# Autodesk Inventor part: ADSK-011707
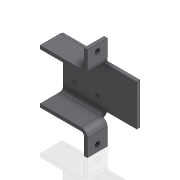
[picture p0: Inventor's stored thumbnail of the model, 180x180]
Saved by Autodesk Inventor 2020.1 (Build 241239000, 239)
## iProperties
Created: 2000-03
Part Number: ADSK-011707
Material: 1.0312 DC05
Document SubType Name: Tôlerie
Designer: cmcgourin
Density: 1 g/cm^3
Sheet Metal Rule: Stahlblech 1.0312 - DC05 -   6.0 mm
Appearance: Metal-Steel(Polish)
Mass: 133.774 g
Surface Area: 504.03 cm^2
Volume: 133.774 cm^3
Sheet Metal Width: 140,000 mm
Sheet Metal Length: 181,143 mm
Sheet Metal Area: 25360,070 mm^2
Flat Pattern Width: 14 cm
Flat Pattern Length: 18.1143 cm
Flat Pattern Area: 253.601 cm^2
Control State: 0
Master: False
Checked Out: False
Shininess: 25.0
Length Units: 11269
Angle Units: 11279
Time Units: 11290
Mass Units: 11283
Length Display Precision: 3
Angle Display Precision: 2
Compacted: True
Cutlength: 23.25
Material Desc: Material Description goes here
Material_Number: Pearson
G_L: 140x181,1 mm
Thickness: 6,000 mm
Dimensions: 178x50x140 mm
Mass: 0,134 kg
Semi finished: Stahlblech 1.0312 - DC05 -   6.0 mm
VLT_Material: 1.0312 DC05
DocNumber: ADSK-011707.ipt
Folder: 01 - Themengebiete\Simplification\01 - Packaging machine\
VDS_Category: 3D Komponenten
Density: 0.0
Volumn: 0.0
Area: 0.0
PropertySet Name: Model Information
Author: cmcgourin
Revision Number: -
Title: holding plate
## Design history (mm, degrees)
sketch "Sketch9"
  geometry: L1 (0, 0)-(38, 0) reference; L2 (38, 0)-(0, 0) reference; 2 further points
  constraints: 1 midpoint, 1 vertical alignment
  dimensions: "d27" = 12.5 distance from line of L1 point (19, -12.5)
node "Hole1" dims "d28" = 9, "d29" = 9.525, "d30" = 6.35, "d31" = 60 deg, "d32" = 19.05, "d33" = 118 deg, "d64" = 6
sketch "Sketch10"
  geometry: L1 (38, 0)-(0, 0) reference; L2 (0, 0)-(38, 0) reference; 2 further points
  constraints: 1 midpoint, 1 vertical alignment
  dimensions: "d34" = 12.5 distance from line of point (19, 12.5) L1
node "Hole2" dims "d35" = 9, "d36" = 9.525, "d37" = 6.35, "d38" = 60 deg, "d39" = 19.05, "d40" = 118 deg, "d65" = 6
sketch "Sketch11"
  geometry: L1 (-65.5, 60.5)-(-22.5, 60.5); L2 (-22.5, 60.5)-(-22.5, 17.5); L3 (-22.5, 17.5)-(-65.5, 17.5); L4 (-65.5, 17.5)-(-65.5, 60.5); L5 (0, 78)-(0, 0) reference; 6 further points
  constraints: 8 end point, 4 coincident, 2 midpoint, 2 parallel, 1 horizontal, 1 horizontal alignment, 1 perpendicular
  dimensions: "d66" = 22.5 distance between parallel lines of L5 L2; "d67" = 43 distance of L1.start L1.end; "d68" = 43 distance of L3.end L1.start (= d67)
node "Hole3" dims "d41" = 6.6, "d42" = 9.525, "d43" = 6.35, "d44" = 60 deg, "d45" = 19.05, "d46" = 118 deg, "d69" = 6
node "Plate1" dims "d59" = 6 (= Thickness)
node "Face1"
  sketch "Sketch2"
    geometry: L1 (-70, 51)-(70, 51); L2 (70, 51)-(70, -51); L3 (70, -51)-(-70, -51); L4 (-70, -51)-(-70, 51); 3 further points
    constraints: 8 end point, 2 midpoint, 2 parallel, 1 horizontal, 1 horizontal alignment, 1 perpendicular, 1 vertical alignment
    dimensions: "d6" = 102 distance of L3.end L1.start; "d7" = 140 distance of L2.end L3.end
node "Plate2" dims "d9" = 44, "d10" = 90 deg, "d11" = 6 (= BendRadius), "d47" = 6 (= BendReliefWidth), "d48" = 3 (= BendReliefDepth), "d49" = 12 (= MinimumRemnant), "d59" = 6 (= Thickness), "d60" = 6 (= TransitionRadius), "SeamGap" = 0.00508
node "Bend1" dims "d9" = 44, "d10" = 90 deg, "d11" = 6 (= BendRadius), "d47" = 6 (= BendReliefWidth), "d48" = 3 (= BendReliefDepth), "d49" = 12 (= MinimumRemnant), "d59" = 6 (= Thickness), "d60" = 6 (= TransitionRadius), "SeamGap" = 0.00508
node "Flange1"
node "Plate4" dims "d15" = 44, "d16" = 90 deg, "d17" = 6 (= BendRadius), "d50" = 6 (= BendReliefWidth), "d51" = 3 (= BendReliefDepth), "d52" = 12 (= MinimumRemnant), "d59" = 6 (= Thickness), "d61" = 6 (= TransitionRadius), "SeamGap" = 0.00508
node "Bend3" dims "d15" = 44, "d16" = 90 deg, "d17" = 6 (= BendRadius), "d50" = 6 (= BendReliefWidth), "d51" = 3 (= BendReliefDepth), "d52" = 12 (= MinimumRemnant), "d59" = 6 (= Thickness), "d61" = 6 (= TransitionRadius), "SeamGap" = 0.00508
node "Flange3"
sketch "Sketch6"
  geometry: L1 (140, 38)-(0, 38) reference; L2 (140, 38)-(140, 0) reference; L3 (140, 0)-(90, 0); L4 (90, 0)-(90, 38); L5 (90, 38)-(140, 38); L6 (140, 38)-(140, 0)
  constraints: 8 end point, 2 parallel, 1 horizontal, 1 perpendicular, 1 point on line
  dimensions: "d18" = 50 distance of L2.end L3.end
node "Cut1" dims "d19" = 6 (= Thickness), "d20" = 0
node "Plate5" dims "d21" = 38, "d22" = 90 deg, "d23" = 6 (= BendRadius), "d53" = 6 (= BendReliefWidth), "d54" = 3 (= BendReliefDepth), "d55" = 12 (= MinimumRemnant), "d59" = 6 (= Thickness), "d62" = 6 (= TransitionRadius), "SeamGap" = 0.00508
node "Bend4" dims "d21" = 38, "d22" = 90 deg, "d23" = 6 (= BendRadius), "d53" = 6 (= BendReliefWidth), "d54" = 3 (= BendReliefDepth), "d55" = 12 (= MinimumRemnant), "d59" = 6 (= Thickness), "d62" = 6 (= TransitionRadius), "SeamGap" = 0.00508
node "Flange4"
node "Plate6" dims "d24" = 38, "d25" = 90 deg, "d26" = 6 (= BendRadius), "d56" = 6 (= BendReliefWidth), "d57" = 3 (= BendReliefDepth), "d58" = 12 (= MinimumRemnant), "d59" = 6 (= Thickness), "d63" = 6 (= TransitionRadius), "SeamGap" = 0.00508
node "Bend5" dims "d24" = 38, "d25" = 90 deg, "d26" = 6 (= BendRadius), "d56" = 6 (= BendReliefWidth), "d57" = 3 (= BendReliefDepth), "d58" = 12 (= MinimumRemnant), "d59" = 6 (= Thickness), "d63" = 6 (= TransitionRadius), "SeamGap" = 0.00508
node "Flange5"
node "Solide1"
node "Corps solides"
node "Corps surfaciques"
sketch "Sketch3"
  geometry: L1 (140, 0)-(140, 44); L2 (140, 44)-(0, 44); 1 other entity
  constraints: 4 end point, 4 other
sketch "Sketch5"
  geometry: L1 (140, 0)-(140, 44); L2 (140, 44)-(0, 44); 1 other entity
  constraints: 4 end point, 4 other
sketch "Sketch7"
  geometry: L1 (0, 38)-(-38, 38); L2 (-38, 38)-(-38, 0); 1 other entity
  constraints: 4 end point, 4 other
sketch "Sketch8"
  geometry: L1 (0, -38)-(38, -38); L2 (38, -38)-(38, 0); 1 other entity
  constraints: 4 end point, 4 other
feature "Definition1"
other parameters: "Thickness" = 6 (derived), "BendRadius" = 6 (= Thickness), "BendReliefWidth" = 6 (= Thickness), "BendReliefDepth" = 3 (= 0.5 x Thickness), "CornerReliefSize" = 24 (= 4 x Thickness), "MinimumRemnant" = 12 (= 2 x Thickness), "d8" = 6 (= BendRadius), "TransitionRadius" = 6 (= BendRadius), "TailleRayonJacobi" = 6 (= BendRadius), "TailleJeu" = 6 (= Thickness), "BendRadius" = 6, "BendReliefDepth" = 3, "BendReliefWidth" = 6, "CornerReliefSize" = 24, "MinimumRemnant" = 12, "TailleJeu" = 6, "TailleRayonJacobi" = 6, "Thickness" = 6, "TransitionRadius" = 6
